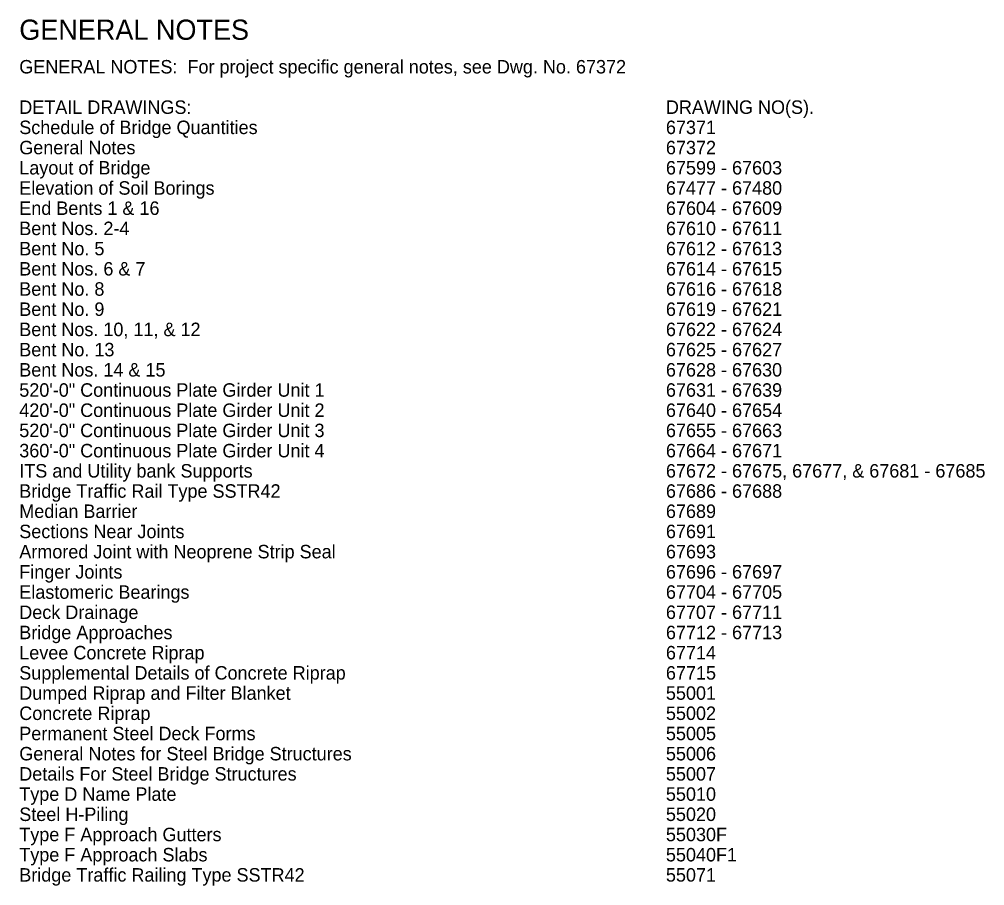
# Model space of a CAD drawing. Extents: x 0.06 to 1.36, y 0.04 to 0.87.
# Drawn here: x 0.0907 to 0.449, y 0.544 to 0.8656 of the extents above; entities that cross this region are included whole.
import ezdxf

# ---------------------------------------------------------------- set-up
doc = ezdxf.new("R2010")
doc.units = 0
doc.layers.add('B_Boring Annot', color=7, linetype='Continuous')
doc.layers.add('R_ROW', color=7, linetype='Continuous')

msp = doc.modelspace()

# ---------------------------------------------------------------- texts
at = {"layer": 'B_Boring Annot'}
for s, p in [('GENERAL NOTES:  For project specific general notes, see Dwg. No. 67372', (0.09071, 0.84552)), ('DETAIL DRAWINGS:', (0.09071, 0.83052)), ('DRAWING NO(S).', (0.33071, 0.83052)), ('Schedule of Bridge Quantities', (0.09071, 0.82302)), ('67371', (0.33071, 0.82302)), ('General Notes', (0.09071, 0.81552)), ('67372 ', (0.33071, 0.81552)), ('Layout of Bridge', (0.09071, 0.80802)), ('67599 - 67603', (0.33071, 0.80802)), ('Elevation of Soil Borings', (0.09071, 0.80052)), ('67477 - 67480', (0.33071, 0.80052)), ('End Bents 1 & 16', (0.09071, 0.79302)), ('67604 - 67609', (0.33071, 0.79302)), ('Bent Nos. 2-4', (0.09071, 0.78552)), ('67610 - 67611', (0.33071, 0.78552)), ('Bent No. 5', (0.09071, 0.77802)), ('67612 - 67613', (0.33071, 0.77802)), ('Bent Nos. 6 & 7', (0.09071, 0.77052)), ('67614 - 67615', (0.33071, 0.77052)), ('Bent No. 8', (0.09071, 0.76302)), ('67616 - 67618', (0.33071, 0.76302)), ('Bent No. 9', (0.09071, 0.75552)), ('67619 - 67621', (0.33071, 0.75552)), ('Bent Nos. 10, 11, & 12', (0.09071, 0.74802)), ('67622 - 67624', (0.33071, 0.74802)), ('Bent No. 13', (0.09071, 0.74052)), ('67625 - 67627', (0.33071, 0.74052)), ('Bent Nos. 14 & 15', (0.09071, 0.73302)), ('67628 - 67630', (0.33071, 0.73302)), ('520\'-0" Continuous Plate Girder Unit 1', (0.09071, 0.72552)), ('67631 - 67639', (0.33071, 0.72552)), ('420\'-0" Continuous Plate Girder Unit 2', (0.09071, 0.71802)), ('67640 - 67654', (0.33071, 0.71802)), ('520\'-0" Continuous Plate Girder Unit 3', (0.09071, 0.71052)), ('67655 - 67663', (0.33071, 0.71052)), ('360\'-0" Continuous Plate Girder Unit 4', (0.09071, 0.70302)), ('67664 - 67671', (0.33071, 0.70302)), ('ITS and Utility bank Supports', (0.09071, 0.69552)), ('67672 - 67675, 67677, & 67681 - 67685', (0.33071, 0.69552)), ('Bridge Traffic Rail Type SSTR42', (0.09071, 0.68802)), ('67686 - 67688', (0.33071, 0.68802)), ('Median Barrier', (0.09071, 0.68052)), ('67689', (0.33071, 0.68052)), ('Sections Near Joints', (0.09071, 0.67302)), ('67691', (0.33071, 0.67302)), ('Armored Joint with Neoprene Strip Seal', (0.09071, 0.66552)), ('67693', (0.33071, 0.66552)), ('Finger Joints', (0.09071, 0.65802)), ('67696 - 67697', (0.33071, 0.65802)), ('Elastomeric Bearings', (0.09071, 0.65052)), ('67704 - 67705', (0.33071, 0.65052)), ('Deck Drainage', (0.09071, 0.64302)), ('67707 - 67711', (0.33071, 0.64302)), ('Bridge Approaches', (0.09071, 0.63552)), ('67712 - 67713', (0.33071, 0.63552)), ('Levee Concrete Riprap', (0.09071, 0.62802)), ('67714', (0.33071, 0.62802)), ('Supplemental Details of Concrete Riprap', (0.09071, 0.62052)), ('67715', (0.33071, 0.62052)), ('Dumped Riprap and Filter Blanket', (0.09071, 0.61302)), ('55001', (0.33071, 0.61302)), ('Concrete Riprap', (0.09071, 0.60552)), ('55002', (0.33071, 0.60552)), ('Permanent Steel Deck Forms', (0.09071, 0.59802)), ('55005', (0.33071, 0.59802)), ('General Notes for Steel Bridge Structures', (0.09071, 0.59052)), ('55006', (0.33071, 0.59052)), ('Details For Steel Bridge Structures', (0.09071, 0.58302)), ('55007', (0.33071, 0.58302)), ('Type D Name Plate', (0.09071, 0.57552)), ('55010', (0.33071, 0.57552)), ('Steel H-Piling', (0.09071, 0.56802)), ('55020', (0.33071, 0.56802)), ('Type F Approach Gutters', (0.09071, 0.56052)), ('55030F', (0.33071, 0.56052)), ('Type F Approach Slabs', (0.09071, 0.55302)), ('55040F1', (0.33071, 0.55302)), ('Bridge Traffic Railing Type SSTR42', (0.09071, 0.54552)), ('55071', (0.33071, 0.54552))]:
    msp.add_text(s, height=0.005, dxfattribs=at).set_placement(p)
at = {"layer": 'R_ROW'}
msp.add_text('GENERAL NOTES', height=0.0075, dxfattribs=at).set_placement((0.09071, 0.85802))

doc.saveas('drawing.dxf')
